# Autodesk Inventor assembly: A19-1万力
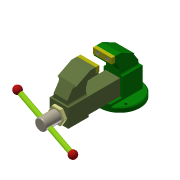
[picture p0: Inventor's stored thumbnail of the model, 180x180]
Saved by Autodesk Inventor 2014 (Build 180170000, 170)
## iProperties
Created: 2008-07
Part Number: A19-1万力
Document SubType Name: Assembly
Designer: y-shimohigashi
Stock Number: A19-1万力
ドキュメント番号: 19
目的: プロパティコピー練習
Author: y-shimohigashi
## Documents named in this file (5)
- \\SVFL01\Data\技術\CAD\Inventor\テキスト\Inventor_教育Text\R2014（仮）\Inventor2014基礎コース\練習問題-19\A19-1万力.iam
- \\SVFL01\Data\技術\CAD\Inventor\テキスト\Inventor_教育Text\R2014（仮）\Inventor2014基礎コース\練習問題-19\A19-8ハンドル部.iam
- \\SVFL01\Data\技術\CAD\Inventor\テキスト\Inventor_教育Text\R2014（仮）\Inventor2014基礎コース\練習問題-19\A19-12.iam
- \\SVFL01\Data\技術\CAD\Inventor\テキスト\Inventor_教育Text\R2014（仮）\Inventor2014基礎コース\練習問題-19\A19-13.iam
- \\SVFL01\Data\技術\CAD\Inventor\テキスト\Inventor_教育Text\R2014（仮）\Inventor2014基礎コース\練習問題-19\A19-14.iam
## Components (4 placed, 4 different names)
1. A19-12:1 [sub-assembly] — メイト:5, メイト:6, メイト:7
2. A19-8ハンドル部:1 [sub-assembly] — メイト:8, メイト:9
3. A19-13:1 [sub-assembly] — メイト:5, メイト:6, メイト:7, 挿入:1
4. A19-14:1 [sub-assembly] — 挿入:1, メイト:8, メイト:9
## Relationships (6: Mate 5, Insert 1)
- メイト:5 [Mate]: A19-12:1 ↔ A19-13:1
- メイト:6 [Mate]: A19-12:1 ↔ A19-13:1
- メイト:7 [Mate]: A19-12:1 ↔ A19-13:1
- 挿入:1 [Insert]: A19-13:1 ↔ A19-14:1
- メイト:8 [Mate]: A19-8ハンドル部:1 ↔ A19-14:1
- メイト:9 [Mate]: A19-8ハンドル部:1 ↔ A19-14:1
